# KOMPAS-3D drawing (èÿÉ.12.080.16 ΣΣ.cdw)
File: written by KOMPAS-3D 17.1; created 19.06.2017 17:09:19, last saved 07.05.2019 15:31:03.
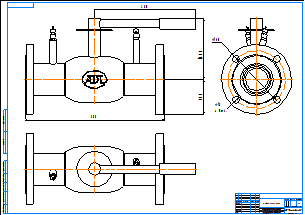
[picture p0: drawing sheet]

Sheet 1: A1, landscape

Title block, sheet 1: name: КШР.12.080.16 фф; material: Внимание! Данный продукт является объектом авторского права ООО «Торговый Дом АДЛ». / Запрещается изменение, копирование, распространение / (в том числе путем копирования на другие сайты и ресурсы в Интернете) / или любое иное использование информации и объектов без предварительного / согласия правообладателя (ООО «Торговый Дом АДЛ»).; scale: 1:1; sheets: 1; organisation: ООО "Торговый дом АДЛ"; sheet format: A1; stored path: C:\Users\tra\Desktop\2д чертежи\Шаровые краны БИВАЛ\КШР_Бивал_серия_12\KOMPAS 2D\КШР.12.080.16 фф.cdw

Views: Спереди 1, Проекционный вид 2, Проекционный вид 3
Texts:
  Klimkovich
  ADL
Dimensions and other numbers on the sheet: 385; 280; 168,8; 97,5; 160; 18; 4 Отв.; 1:1; 1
